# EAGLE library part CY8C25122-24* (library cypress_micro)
The CY8C25xxx/26xxx family of Programmable System-on-Chip (PSoC) microcontrollers offers a fast core, Flash program memory and SRAM data memory with configurable analog and digital peripheral blocks in a range of convinient pinouts and memory size on one single chip.
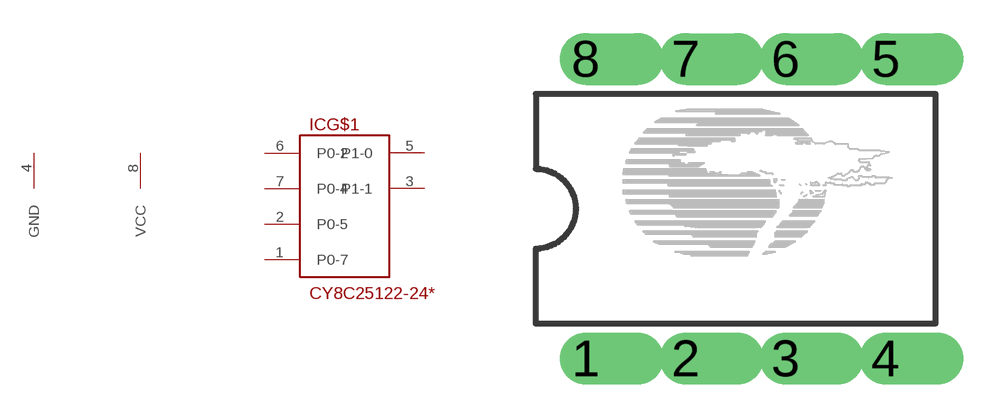
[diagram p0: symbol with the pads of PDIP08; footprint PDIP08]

Designator prefix IC; gates G$1=CY8C25122 G$2=GND G$3=VCC

## CY8C25122-24PI  [PDIP08]
1  G$1:P0-7
2  G$1:P0-5
3  G$1:P1-1
4  G$2:GND  pwr
5  G$1:P1-0
6  G$1:P0-2
7  G$1:P0-4
8  G$3:VCC  pwr

## Footprint PDIP08 (pad centres in mm)
Plastic Dual Inline Package with 8 pins
drill 0.813 offset: 1 -3.81,-3.81; 2 -1.27,-3.81; 3 1.27,-3.81; 4 3.81,-3.81; 5 3.81,3.81; 6 1.27,3.81; 7 -1.27,3.81; 8 -3.81,3.81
